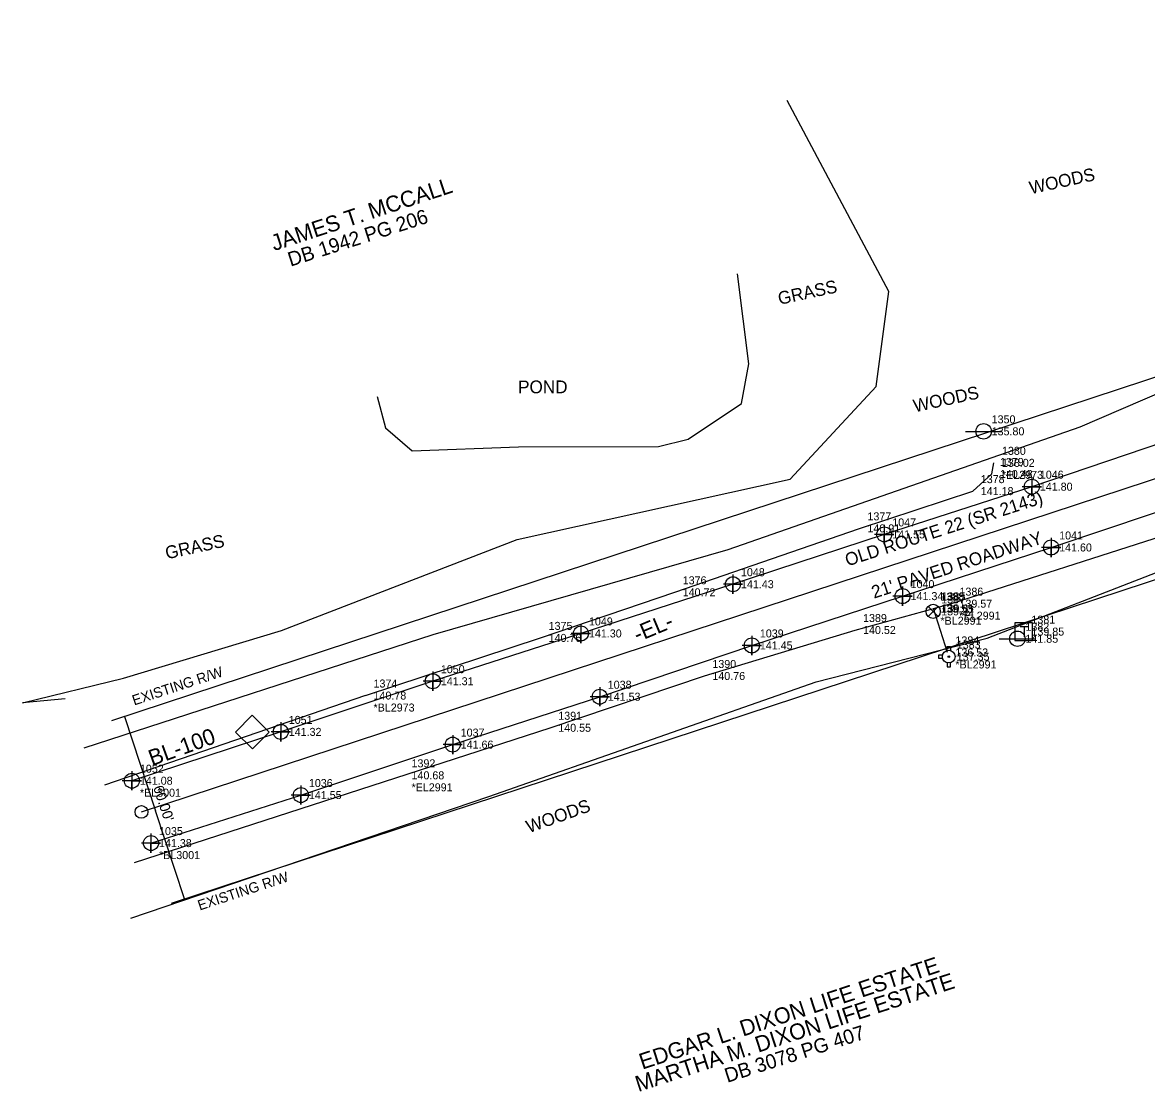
# Model space of a CAD drawing. Extents: x 2248240 to 2249086, y 672625 to 673467.
# Drawn here: x 2248240.2 to 2248591.2, y 672843.9 to 673177.9 of the extents above; entities that cross this region are included whole.
import ezdxf

# ---------------------------------------------------------------- set-up
doc = ezdxf.new("R2010")
doc.units = 0
for name, color, linetype in [('CTL Supplemental Horizontal and Vertical CELL', 7, 'Continuous'), ('CTL Supplemental Horizontal and Vertical Text', 7, 'Continuous'), ('Exist Horizontal Alignment', 7, 'Continuous'), ('Exist Horizontal Alignment Direction Label', 7, 'Continuous'), ('Exist Horizontal Alignment Point', 7, 'Continuous'), ('Exist Hydro Stream or Body of Water', 7, 'Continuous'), ('Exist Hydro Stream or Body of Water Text', 7, 'Continuous'), ('Exist Property Deed Book Text', 7, 'Continuous'), ('Exist Property Owner Text', 7, 'Continuous'), ('Exist Right of Way Line', 7, 'Continuous'), ('Exist Right of Way Line Text', 7, 'Continuous'), ('Exist Right of Way Width CELL', 7, 'Continuous'), ('Exist Roads EOP', 7, 'Continuous'), ('Exist Roads EOP Cogo Comment', 7, 'Continuous'), ('Exist Roads EOP Cogo Elevation', 7, 'Continuous'), ('Exist Roads EOP Cogo Number', 7, 'Continuous'), ('Exist Roads EOP Cogo Point CELL', 7, 'Continuous'), ('Exist Roads EOP Text', 7, 'Continuous'), ('Exist Utilities Telephone Pedestal CELL', 7, 'Continuous'), ('Exist Utilities Telephone Pedestal Cogo Elevation', 7, 'Continuous'), ('Exist Utilities Telephone Pedestal Cogo Number', 7, 'Continuous'), ('Exist Utilities Telephone Pole CELL', 7, 'Continuous'), ('Exist Utilities Telephone Pole Cogo Elevation', 7, 'Continuous'), ('Exist Utilities Telephone Pole Cogo Number', 7, 'Continuous'), ('Exist Utilities Telephone UG FO SUE LOS B', 7, 'Continuous'), ('Exist Utilities Telephone UG FO SUE LOS B Cogo Comment', 7, 'Continuous'), ('Exist Utilities Telephone UG FO SUE LOS B Cogo Elevation', 7, 'Continuous'), ('Exist Utilities Telephone UG FO SUE LOS B Cogo Number', 7, 'Continuous'), ('Exist Utilities Water Fire Hydrant CELL', 7, 'Continuous'), ('Exist Utilities Water Fire Hydrant Cogo Elevation', 7, 'Continuous'), ('Exist Utilities Water Fire Hydrant Cogo Number', 7, 'Continuous'), ('Exist Utilities Water UG Line SUE LOS B', 7, 'Continuous'), ('Exist Utilities Water UG Line SUE LOS B Cogo Comment', 7, 'Continuous'), ('Exist Utilities Water UG Line SUE LOS B Cogo Elevation', 7, 'Continuous'), ('Exist Utilities Water UG Line SUE LOS B Cogo Number', 7, 'Continuous'), ('Exist Utilities Water UG Line SUE LOS C', 7, 'Continuous'), ('Exist Utilities Water Valve CELL', 7, 'Continuous'), ('Exist Utilities Water Valve Cogo Elevation', 7, 'Continuous'), ('Exist Utilities Water Valve Cogo Number', 7, 'Continuous'), ('Exist Vegetation Woods Line', 7, 'Continuous'), ('Exist Vegetation Woods Line Text', 7, 'Continuous')]:
    doc.layers.add(name, color=color, linetype=linetype)

msp = doc.modelspace()

# ---------------------------------------------------------------- linework, layer by layer
at = {"layer": 'CTL Supplemental Horizontal and Vertical CELL'}
msp.add_line((2248311.96, 672956.14), (2248311.96, 672956.14), dxfattribs=at)
msp.add_lwpolyline([(2248306.75, 672956.16), (2248311.99, 672961.4), (2248317.24, 672956.15), (2248312, 672950.91)], close=True, dxfattribs=at)
at = {"layer": 'Exist Horizontal Alignment'}
msp.add_line((2248277.37, 672931.22), (2248730.23, 673080.25), dxfattribs=at)
at = {"layer": 'Exist Horizontal Alignment Point'}
msp.add_circle((2248277.37, 672931.22), 2, dxfattribs=at)
at = {"layer": 'Exist Hydro Stream or Body of Water'}
for points in [[(2248448.11, 673047.72), (2248464.69, 673058.79), (2248467, 673071.21), (2248463.51, 673099.3)], [(2248350.95, 673060.98), (2248353.59, 673051.18), (2248361.85, 673044.03), (2248395.13, 673045.33), (2248438.87, 673045.37)], [(2248438.87, 673045.37), (2248448.11, 673047.72)]]:
    msp.add_lwpolyline(points, dxfattribs=at)
at = {"layer": 'Exist Right of Way Line'}
for p, q in [((2248716.39, 673107.27), (2248267.99, 672959.72)), ((2248286.75, 672902.73), (2248735.14, 673050.28))]:
    msp.add_line(p, q, dxfattribs=at)
at = {"layer": 'Exist Right of Way Width CELL'}
for p in [(2248272.09, 672961.07), (2248290.84, 672904.07)]:
    msp.add_line(p, (2248281.8, 672931.55), dxfattribs=at)
at = {"layer": 'Exist Roads EOP'}
msp.add_lwpolyline([(2248280.35, 672921.48), (2248327.15, 672936.49), (2248374.55, 672952.25), (2248420.47, 672967.21), (2248467.96, 672983.23), (2248515.03, 672998.64), (2248561.42, 673013.84), (2248608.93, 673029.8), (2248624.52, 673032.49), (2248616.71, 673054.88), (2248602.35, 673048.76), (2248555.39, 673032.83), (2248509.31, 673017.92), (2248462.07, 673002.36), (2248414.6, 672986.98), (2248368.35, 672972.05), (2248320.86, 672956.23), (2248274.38, 672940.97)], dxfattribs=at)
at = {"layer": 'Exist Roads EOP Cogo Point CELL'}
for points in [[(2248555.39, 673035.83), (2248555.39, 673029.83), (2248555.39, 673032.83), (2248558.39, 673032.83), (2248552.39, 673032.83)], [(2248509.31, 673020.92), (2248509.31, 673014.92), (2248509.31, 673017.92), (2248512.31, 673017.92), (2248506.31, 673017.92)], [(2248561.42, 673016.84), (2248561.42, 673010.84), (2248561.42, 673013.84), (2248564.42, 673013.84), (2248558.42, 673013.84)], [(2248462.07, 673005.36), (2248462.07, 672999.36), (2248462.07, 673002.36), (2248465.07, 673002.36), (2248459.07, 673002.36)], [(2248515.03, 673001.64), (2248515.03, 672995.64), (2248515.03, 672998.64), (2248518.03, 672998.64), (2248512.03, 672998.64)], [(2248414.6, 672989.98), (2248414.6, 672983.98), (2248414.6, 672986.98), (2248417.6, 672986.98), (2248411.6, 672986.98)], [(2248467.96, 672986.23), (2248467.96, 672980.23), (2248467.96, 672983.23), (2248470.96, 672983.23), (2248464.96, 672983.23)], [(2248368.35, 672975.05), (2248368.35, 672969.05), (2248368.35, 672972.05), (2248371.35, 672972.05), (2248365.35, 672972.05)], [(2248420.47, 672970.21), (2248420.47, 672964.21), (2248420.47, 672967.21), (2248423.47, 672967.21), (2248417.47, 672967.21)], [(2248320.86, 672959.23), (2248320.86, 672953.23), (2248320.86, 672956.23), (2248323.86, 672956.23), (2248317.86, 672956.23)], [(2248374.55, 672955.25), (2248374.55, 672949.25), (2248374.55, 672952.25), (2248377.55, 672952.25), (2248371.55, 672952.25)], [(2248274.38, 672943.97), (2248274.38, 672937.97), (2248274.38, 672940.97), (2248277.38, 672940.97), (2248271.38, 672940.97)], [(2248327.15, 672939.49), (2248327.15, 672933.49), (2248327.15, 672936.49), (2248330.15, 672936.49), (2248324.15, 672936.49)], [(2248280.35, 672924.48), (2248280.35, 672918.48), (2248280.35, 672921.48), (2248283.35, 672921.48), (2248277.35, 672921.48)]]:
    msp.add_lwpolyline(points, dxfattribs=at)
for centre in [(2248555.39, 673032.83), (2248509.31, 673017.92), (2248561.42, 673013.84), (2248462.07, 673002.36), (2248515.03, 672998.64), (2248414.6, 672986.98), (2248467.96, 672983.23), (2248368.35, 672972.05), (2248420.47, 672967.21), (2248320.86, 672956.23), (2248374.55, 672952.25), (2248274.38, 672940.97), (2248327.15, 672936.49), (2248280.35, 672921.48)]:
    msp.add_circle(centre, 2.34, dxfattribs=at)
at = {"layer": 'Exist Utilities Telephone Pedestal CELL'}
msp.add_line((2248552.77, 672987.55), (2248552.77, 672987.55), dxfattribs=at)
msp.add_lwpolyline([(2248550.04, 672984.73), (2248555.64, 672984.73), (2248555.64, 672990.32), (2248550.04, 672990.32), (2248550.04, 672984.73)], dxfattribs=at)
at = {"layer": 'Exist Utilities Telephone Pole CELL'}
for p, q in [((2248534.66, 673050.12), (2248546, 673050.12)), ((2248540.34, 673050.12), (2248540.34, 673050.12)), ((2248545.22, 672985.32), (2248556.55, 672985.32)), ((2248550.89, 672985.32), (2248550.89, 672985.32))]:
    msp.add_line(p, q, dxfattribs=at)
for centre in [(2248540.34, 673050.12), (2248550.89, 672985.32)]:
    msp.add_circle(centre, 2.41, dxfattribs=at)
at = {"layer": 'Exist Utilities Telephone UG FO SUE LOS B'}
msp.add_line((2248347.33, 672967.58), (2248265.81, 672939.55), dxfattribs=at)
msp.add_lwpolyline([(2248347.33, 672967.58), (2248402.01, 672985.59), (2248443.87, 672999.83), (2248501.56, 673019.81), (2248536.95, 673031.44), (2248542.92, 673036.8), (2248543.56, 673040.28)], dxfattribs=at)
at = {"layer": 'Exist Utilities Water Fire Hydrant CELL'}
msp.add_line((2248529.46, 672979.73), (2248529.46, 672979.73), dxfattribs=at)
for points in [[(2248527.54, 672980.24), (2248526.25, 672980.24), (2248526.25, 672979.22), (2248527.54, 672979.22)], [(2248528.94, 672981.64), (2248528.94, 672982.93), (2248529.97, 672982.93), (2248529.97, 672981.62)], [(2248528.94, 672977.82), (2248528.94, 672976.53), (2248529.97, 672976.53), (2248529.97, 672977.84)]]:
    msp.add_lwpolyline(points, dxfattribs=at)
for radius in [1.98, 0.243]:
    msp.add_circle((2248529.46, 672979.73), radius, dxfattribs=at)
at = {"layer": 'Exist Utilities Water UG Line SUE LOS B'}
for points in [[(2248275.19, 672915.4), (2248405.02, 672957.51), (2248453.14, 672973.69), (2248500.19, 672988.05), (2248524.35, 672994.71)], [(2248529.03, 672981.04), (2248524.71, 672994.79), (2248530.3, 672996.29)]]:
    msp.add_lwpolyline(points, dxfattribs=at)
at = {"layer": 'Exist Utilities Water UG Line SUE LOS C'}
msp.add_line((2248530.3, 672996.29), (2248853.08, 673100.11), dxfattribs=at)
at = {"layer": 'Exist Utilities Water Valve CELL'}
msp.add_lwpolyline([(2248526.16, 672995.44), (2248523.01, 672992.29), (2248524.58, 672993.87), (2248526.16, 672992.29), (2248523.01, 672995.44)], dxfattribs=at)
msp.add_circle((2248524.58, 672993.87), 2.23, dxfattribs=at)
at = {"layer": 'Exist Vegetation Woods Line'}
for points in [[(2248682.79, 673177.86), (2248667.65, 673115.13), (2248663.64, 673091.64), (2248570.37, 673051.47), (2248460.42, 673013.15), (2248368.39, 672986.57), (2248259.41, 672951.1)], [(2248253.57, 672966.51), (2248240.22, 672965.29), (2248271.72, 672973.02), (2248321.14, 672987.85), (2248394.64, 673016.28), (2248479.88, 673035.13), (2248506.75, 673064.18), (2248510.76, 673093.85), (2248478.95, 673153.49)], [(2248274.03, 672898.01), (2248385.83, 672936.02), (2248488.06, 672971.87), (2248541.49, 672985.46), (2248652.67, 673028.73), (2248668.11, 673032.44), (2248686.33, 672939.73)]]:
    msp.add_lwpolyline(points, dxfattribs=at)

# ---------------------------------------------------------------- texts
at = {"layer": 'CTL Supplemental Horizontal and Vertical Text'}
msp.add_text('BL-100', height=5, rotation=19.896, dxfattribs=at).set_placement((2248280.66, 672945.51))
at = {"layer": 'Exist Horizontal Alignment Direction Label'}
msp.add_text('-EL-', height=5, rotation=22.669, dxfattribs=at).set_placement((2248432.27, 672984.17))
at = {"layer": 'Exist Hydro Stream or Body of Water Text'}
msp.add_text('POND', height=4, rotation=0.0567, dxfattribs=at).set_placement((2248394.97, 673062))
at = {"layer": 'Exist Property Deed Book Text'}
for s, p in [('DB 1942 PG 206', (2248323.92, 673101.54)), ('DB 3078 PG 407', (2248460.29, 672846.57))]:
    msp.add_text(s, height=4.5, rotation=17.6961, dxfattribs=at).set_placement(p)
at = {"layer": 'Exist Property Owner Text'}
for s, p in [('JAMES T. MCCALL', (2248318.78, 673106.41)), ('EDGAR L. DIXON LIFE ESTATE', (2248433.76, 672850.68)), ('MARTHA M. DIXON LIFE ESTATE', (2248432.53, 672843.69))]:
    msp.add_text(s, height=5, rotation=18.1871, dxfattribs=at).set_placement(p)
at = {"layer": 'Exist Right of Way Line Text'}
for p in [(2248275.1, 672964.45), (2248295.56, 672900.4)]:
    msp.add_text('EXISTING R/W', height=3.2, rotation=18.2144, dxfattribs=at).set_placement(p)
at = {"layer": 'Exist Right of Way Width CELL'}
msp.add_text("60.00'", height=3.2, rotation=288.2144, dxfattribs=at).set_placement((2248280.99, 672938.89))
at = {"layer": 'Exist Roads EOP Cogo Comment'}
for s, p in [('*EL3001', (2248276.88, 672935.97)), ('*BL3001', (2248282.85, 672916.48))]:
    msp.add_text(s, height=2.5, dxfattribs=at).set_placement(p)
at = {"layer": 'Exist Roads EOP Cogo Elevation'}
for s, p in [('141.80', (2248557.89, 673031.58)), ('141.55', (2248511.81, 673016.67)), ('141.60', (2248563.92, 673012.59)), ('141.43', (2248464.57, 673001.11)), ('141.34', (2248517.53, 672997.39)), ('141.30', (2248417.1, 672985.73)), ('141.45', (2248470.46, 672981.98)), ('141.31', (2248370.85, 672970.8)), ('141.53', (2248422.97, 672965.96)), ('141.32', (2248323.36, 672954.98)), ('141.66', (2248377.05, 672951)), ('141.08', (2248276.88, 672939.72)), ('141.55', (2248329.65, 672935.24)), ('141.38', (2248282.85, 672920.23))]:
    msp.add_text(s, height=2.5, dxfattribs=at).set_placement(p)
at = {"layer": 'Exist Roads EOP Cogo Number'}
for s, p in [('1046', (2248557.89, 673035.33)), ('1047', (2248511.81, 673020.42)), ('1041', (2248563.92, 673016.34)), ('1048', (2248464.57, 673004.86)), ('1040', (2248517.53, 673001.14)), ('1049', (2248417.1, 672989.48)), ('1039', (2248470.46, 672985.73)), ('1050', (2248370.85, 672974.55)), ('1038', (2248422.97, 672969.71)), ('1051', (2248323.36, 672958.73)), ('1037', (2248377.05, 672954.75)), ('1052', (2248276.88, 672943.47)), ('1036', (2248329.65, 672938.99)), ('1035', (2248282.85, 672923.98))]:
    msp.add_text(s, height=2.5, dxfattribs=at).set_placement(p)
at = {"layer": 'Exist Roads EOP Text'}
for s, rotation, p in [('OLD ROUTE 22 (SR 2143)', 17.9262, (2248497.83, 673007.9)), ("21' PAVED ROADWAY", 18.1419, (2248506.1, 672997.82))]:
    msp.add_text(s, height=4, rotation=rotation, dxfattribs=at).set_placement(p)
at = {"layer": 'Exist Utilities Telephone Pedestal CELL'}
msp.add_text('T', height=3.42, dxfattribs=at).set_placement((2248551.64, 672985.84))
at = {"layer": 'Exist Utilities Telephone Pedestal Cogo Elevation'}
msp.add_text('139.85', height=2.5, dxfattribs=at).set_placement((2248555.27, 672986.3))
at = {"layer": 'Exist Utilities Telephone Pedestal Cogo Number'}
msp.add_text('1381', height=2.5, dxfattribs=at).set_placement((2248555.27, 672990.05))
at = {"layer": 'Exist Utilities Telephone Pole Cogo Elevation'}
for s, p in [('135.80', (2248542.84, 673048.87)), ('141.85', (2248553.39, 672984.07))]:
    msp.add_text(s, height=2.5, dxfattribs=at).set_placement(p)
at = {"layer": 'Exist Utilities Telephone Pole Cogo Number'}
for s, p in [('1350', (2248542.84, 673052.62)), ('1382', (2248553.39, 672987.82))]:
    msp.add_text(s, height=2.5, dxfattribs=at).set_placement(p)
at = {"layer": 'Exist Utilities Telephone UG FO SUE LOS B Cogo Comment'}
for s, p in [('*EL2973', (2248546.06, 673035.28)), ('*EL2973', (2248546.06, 673035.28)), ('*BL2973', (2248349.83, 672962.58)), ('*BL2973', (2248349.83, 672962.58))]:
    msp.add_text(s, height=2.5, dxfattribs=at).set_placement(p)
at = {"layer": 'Exist Utilities Telephone UG FO SUE LOS B Cogo Elevation'}
for s, p in [('138.02', (2248546.06, 673039.03)), ('138.02', (2248546.06, 673039.03)), ('140.48', (2248545.42, 673035.55)), ('140.48', (2248545.42, 673035.55)), ('141.18', (2248539.45, 673030.19)), ('141.18', (2248539.45, 673030.19)), ('140.91', (2248504.06, 673018.56)), ('140.91', (2248504.06, 673018.56)), ('140.72', (2248446.37, 672998.58)), ('140.72', (2248446.37, 672998.58)), ('140.76', (2248404.51, 672984.34)), ('140.76', (2248404.51, 672984.34)), ('140.78', (2248349.83, 672966.33)), ('140.78', (2248349.83, 672966.33))]:
    msp.add_text(s, height=2.5, dxfattribs=at).set_placement(p)
at = {"layer": 'Exist Utilities Telephone UG FO SUE LOS B Cogo Number'}
for s, p in [('1380', (2248546.06, 673042.78)), ('1380', (2248546.06, 673042.78)), ('1379', (2248545.42, 673039.3)), ('1379', (2248545.42, 673039.3)), ('1378', (2248539.45, 673033.94)), ('1378', (2248539.45, 673033.94)), ('1377', (2248504.06, 673022.31)), ('1377', (2248504.06, 673022.31)), ('1376', (2248446.37, 673002.33)), ('1376', (2248446.37, 673002.33)), ('1375', (2248404.51, 672988.09)), ('1375', (2248404.51, 672988.09)), ('1374', (2248349.83, 672970.08)), ('1374', (2248349.83, 672970.08))]:
    msp.add_text(s, height=2.5, dxfattribs=at).set_placement(p)
at = {"layer": 'Exist Utilities Water Fire Hydrant Cogo Elevation'}
msp.add_text('137.35', height=2.5, dxfattribs=at).set_placement((2248531.96, 672978.48))
at = {"layer": 'Exist Utilities Water Fire Hydrant Cogo Number'}
msp.add_text('1383', height=2.5, dxfattribs=at).set_placement((2248531.96, 672982.23))
at = {"layer": 'Exist Utilities Water UG Line SUE LOS B Cogo Comment'}
for s, p in [('*EL2991', (2248532.8, 672991.29)), ('*EL2991', (2248532.8, 672991.29)), ('*BL2991', (2248526.85, 672989.71)), ('*BL2991', (2248526.85, 672989.71)), ('*BL2991', (2248531.53, 672976.04)), ('*BL2991', (2248531.53, 672976.04)), ('*EL2991', (2248361.7, 672937.65)), ('*EL2991', (2248361.7, 672937.65))]:
    msp.add_text(s, height=2.5, dxfattribs=at).set_placement(p)
at = {"layer": 'Exist Utilities Water UG Line SUE LOS B Cogo Elevation'}
for s, p in [('139.57', (2248532.8, 672995.04)), ('139.57', (2248532.8, 672995.04)), ('139.53', (2248526.85, 672993.46)), ('139.53', (2248526.85, 672993.46)), ('139.61', (2248527.21, 672993.54)), ('139.61', (2248527.21, 672993.54)), ('140.52', (2248502.69, 672986.8)), ('140.52', (2248502.69, 672986.8)), ('136.53', (2248531.53, 672979.79)), ('136.53', (2248531.53, 672979.79)), ('140.76', (2248455.64, 672972.44)), ('140.76', (2248455.64, 672972.44)), ('140.55', (2248407.52, 672956.26)), ('140.55', (2248407.52, 672956.26)), ('140.68', (2248361.7, 672941.4)), ('140.68', (2248361.7, 672941.4))]:
    msp.add_text(s, height=2.5, dxfattribs=at).set_placement(p)
at = {"layer": 'Exist Utilities Water UG Line SUE LOS B Cogo Number'}
for s, p in [('1386', (2248532.8, 672998.79)), ('1386', (2248532.8, 672998.79)), ('1388', (2248526.85, 672997.21)), ('1388', (2248526.85, 672997.21)), ('1385', (2248527.21, 672997.29)), ('1385', (2248527.21, 672997.29)), ('1389', (2248502.69, 672990.55)), ('1389', (2248502.69, 672990.55)), ('1384', (2248531.53, 672983.54)), ('1384', (2248531.53, 672983.54)), ('1390', (2248455.64, 672976.19)), ('1390', (2248455.64, 672976.19)), ('1391', (2248407.52, 672960.01)), ('1391', (2248407.52, 672960.01)), ('1392', (2248361.7, 672945.15)), ('1392', (2248361.7, 672945.15))]:
    msp.add_text(s, height=2.5, dxfattribs=at).set_placement(p)
at = {"layer": 'Exist Utilities Water Valve Cogo Elevation'}
msp.add_text('139.32', height=2.5, dxfattribs=at).set_placement((2248527.08, 672992.62))
at = {"layer": 'Exist Utilities Water Valve Cogo Number'}
msp.add_text('1387', height=2.5, dxfattribs=at).set_placement((2248527.08, 672996.37))
at = {"layer": 'Exist Vegetation Woods Line Text'}
for s, rotation, p in [('WOODS', 12.2718, (2248555.07, 673124.18)), ('GRASS', 12.2718, (2248476.6, 673089.61)), ('WOODS', 12.2718, (2248518.86, 673056.04)), ('GRASS', 12.2718, (2248285.28, 673010.12)), ('WOODS', 19.6529, (2248398.35, 672924.56))]:
    msp.add_text(s, height=4, rotation=rotation, dxfattribs=at).set_placement(p)

doc.saveas('drawing.dxf')
